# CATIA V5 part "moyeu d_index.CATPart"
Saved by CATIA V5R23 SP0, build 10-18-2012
Part number: moyeu d_index
Definition: moyeu d_index
Source: made
Bounding box of the stored display mesh (mm): x 89 to 121, y -26 to 26, z -26 to 26
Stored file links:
  C:\wamp\www\COURS\CONCEPTION GMP1\TITRE 01-CATIA VOLUMIQUE\05--ACTIONNEUR DE VANNE\prof\CORRECTION\Assemblage\moyeu d_index.CATPart
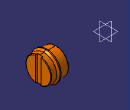
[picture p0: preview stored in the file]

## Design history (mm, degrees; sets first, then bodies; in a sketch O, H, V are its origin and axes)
Body1 "NONE" (main body)
  Solid1 "Manifold Solid #1024": solid without history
